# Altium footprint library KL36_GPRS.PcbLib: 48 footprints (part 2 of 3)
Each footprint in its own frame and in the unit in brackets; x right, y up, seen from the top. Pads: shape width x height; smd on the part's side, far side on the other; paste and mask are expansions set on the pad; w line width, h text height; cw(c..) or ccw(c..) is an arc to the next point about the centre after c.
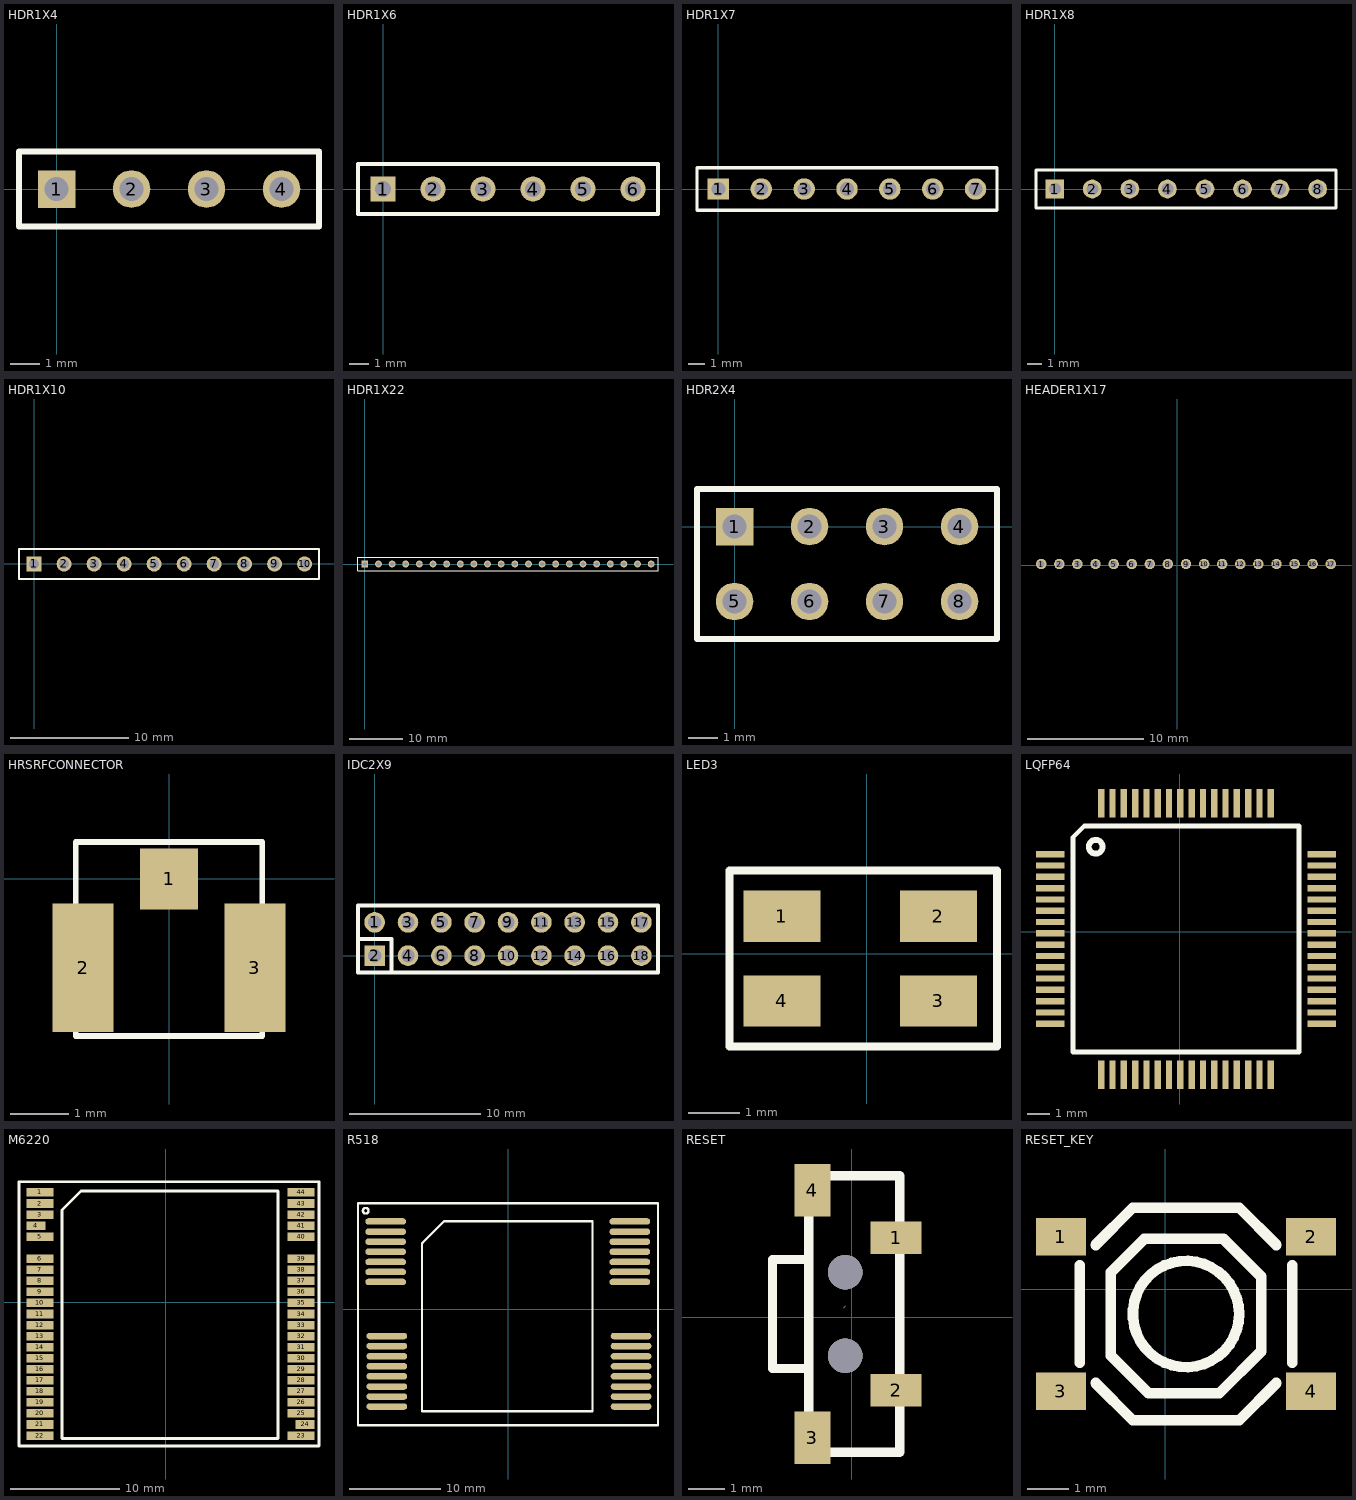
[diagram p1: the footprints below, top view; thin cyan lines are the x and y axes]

## HDR1X4 [mil]
pads (4):
  rect 50x50 hole 32: 1(0,0)
  round 50 hole 32: 2(100,0) 3(200,0) 4(300,0)
Top Overlay:
  lines w7.87: -50,-50 350,-50 350,50 -50,50 -50,-50

## HDR1X6 [mil]
pads (6):
  rect 50x50 hole 32: 1(0,0)
  round 50 hole 32: 2(100,0) 3(200,0) 4(300,0) 5(400,0) 6(500,0)
Top Overlay:
  lines w7.87: -50,-50 550,-50 550,50 -50,50 -50,-50

## HDR1X7 [mil]
pads (7):
  rect 50x50 hole 32: 1(0,0)
  round 50 hole 32: 2(100,0) 3(200,0) 4(300,0) 5(400,0) 6(500,0) 7(600,0)
Top Overlay:
  lines w7.87: -50,-50 -50,50 650,50 650,-50 -50,-50

## HDR1X8 [mil]
pads (8):
  rect 50x50 hole 32: 1(0,0)
  round 50 hole 32: 2(100,0) 3(200,0) 4(300,0) 5(400,0) 6(500,0) 7(600,0) 8(700,0)
Top Overlay:
  lines w7.87: -50,-50 749,-50 749,50 -50,50 -50,-50

## HDR1X10 [mil]
pads (10):
  rect 50x50 hole 32: 1(0,0)
  round 50 hole 32: 2(100,0) 3(200,0) 4(300,0) 5(400,0) 6(500,0) 7(600,0) 8(701,0) 9(801,0) 10(901,0)
Top Overlay:
  lines w7.87: -50,-50 949,-50 949,50 -50,50 -50,-50

## HDR1X22 [mil]
pads (22):
  rect 50x50 hole 32: 1(0,0)
  round 50 hole 32: 2(100,0) 3(200,0) 4(300,0) 5(400,0) 6(500,0) 7(600,0) 8(700,0) 9(800,0) 10(900,0) 11(1000,0) 12(1100,0) 13(1200,0) 14(1300,0) 15(1400,0) 16(1500,0) 17(1600,0) 18(1700,0) 19(1800,0) 20(1900,0) 21(2000,0) 22(2100,0)
Top Overlay:
  lines w7.87: -50,-50 -50,50 25,50 2150,50 2150,-50 -50,-50

## HDR2X4 [mil]
pads (8):
  rect 50x50 hole 32: 1(0,0)
  round 50 hole 32: 2(100,0) 3(200,0) 4(300,0) 5(0,-100) 6(100,-100) 7(200,-100) 8(300,-100)
Top Overlay:
  lines w7.87: -50,-150 350,-150 350,50 -50,50 -50,-150

## HEADER1X17 [mm]
pads (17):
  round 0.9 / inner rect 0.9x1 / far side rect 0.9x2 hole 0.6: 1(-11.733,0.102) 2(-10.173,0.102) 3(-8.613,0.102) 4(-7.053,0.102) 5(-5.493,0.102) 6(-3.933,0.102) 7(-2.373,0.102) 8(-0.813,0.102) 9(0.747,0.102) 10(2.307,0.102) 11(3.867,0.102) 12(5.427,0.102) 13(6.987,0.102) 14(8.547,0.102) 15(10.107,0.102) 16(11.667,0.102) 17(13.227,0.102)

## HRSRFCONNECTOR [mm] "U.FL-R-SMT-1(10)"
height 1.524
pads (3):
  rect 1x1.05 smd: 1(0,0)
  rect 1.05x2.2 smd: 2(-1.475,-1.525) 3(1.475,-1.525)
Top Overlay:
  lines w0.1: -1.6,-2.7 -1.6,0.635 1.6,0.635 1.6,-2.7 -1.6,-2.7

## IDC2X9 [mil]
pads (18):
  round 62 hole 40: 1(0,100) 3(100,100) 4(100,0) 5(200,100) 6(200,0) 7(300,100) 8(300,0) 9(400,100) 10(400,0) 11(500,100) 12(500,0) 13(600,100) 14(600,0) 15(700,100) 16(700,0) 17(800,100) 18(800,0)
  rect 62x62 hole 40: 2(0,0)
Top Overlay:
  lines w12: -50,50 50,50 50,-50 ; -50,-50 850,-50 850,150 -50,150 -50,-50

## LED3 [mil]
pads (5):
  round 40 on Top Overlay: 0(-110,74)
  rect 59.06x39.37 smd: 1(-65,29) 2(55,29) 3(55,-36) 4(-65,-36)
Top Overlay:
  lines w6: -105,-71 100,-71 100,64 -105,64 -105,-71

## LQFP64 [mm]
pads (64):
  rect 1.27x0.28 smd: 1(-5.715,3.429) 2(-5.715,2.929) 3(-5.715,2.429) 4(-5.715,1.929) 5(-5.715,1.429) 6(-5.715,0.929) 7(-5.715,0.429) 8(-5.715,-0.071) 9(-5.715,-0.571) 10(-5.715,-1.071) 11(-5.715,-1.571) 12(-5.715,-2.071) 13(-5.715,-2.571) 14(-5.715,-3.071) 15(-5.715,-3.571) 16(-5.715,-4.071) 33(6.285,-4.071) 34(6.285,-3.571) 35(6.285,-3.071) 36(6.285,-2.571) 37(6.285,-2.071) 38(6.285,-1.571) 39(6.285,-1.071) 40(6.285,-0.571) 41(6.285,-0.071) 42(6.285,0.429) 43(6.285,0.929) 44(6.285,1.429) 45(6.285,1.929) 46(6.285,2.429) 47(6.285,2.929) 48(6.285,3.429)
  rect 0.28x1.27 smd: 17(-3.465,-6.321) 18(-2.965,-6.321) 19(-2.465,-6.321) 20(-1.965,-6.321) 21(-1.465,-6.321) 22(-0.965,-6.321) 23(-0.465,-6.321) 24(0.035,-6.321) 25(0.535,-6.321) 26(1.035,-6.321) 27(1.535,-6.321) 28(2.035,-6.321) 29(2.535,-6.321) 30(3.035,-6.321) 31(3.535,-6.321) 32(4.035,-6.321) 49(4.035,5.679) 50(3.535,5.679) 51(3.035,5.679) 52(2.535,5.679) 53(2.035,5.679) 54(1.535,5.679) 55(1.035,5.679) 56(0.535,5.679) 57(0.035,5.679) 58(-0.465,5.679) 59(-0.965,5.679) 60(-1.465,5.679) 61(-1.965,5.679) 62(-2.465,5.679) 63(-2.965,5.679) 64(-3.465,5.679)
Top Overlay:
  circle w0.254: c-3.709,3.759 r0.306
  lines w0.203: -4.715,-5.321 5.285,-5.321 5.285,4.679 -4.215,4.679 -4.715,4.179 -4.715,-5.321

## M6220 [mil]
pads (44):
  rect 98.43x30.96 smd: 1(-456,397) 2(-456,357) 3(-456,317) 5(-456,237) 6(-456,157) 7(-456,117) 8(-456,77) 9(-456,37) 10(-456,-3) 11(-456,-43) 12(-456,-83) 13(-456,-123) 14(-456,-163) 15(-456,-203) 16(-456,-243) 17(-456,-283) 18(-456,-323) 19(-456,-363) 20(-456,-403) 21(-456,-443) 22(-456,-483) 23(489,-483) 25(489,-403) 26(489,-363) 27(489,-323) 28(489,-283) 29(489,-243) 30(489,-203) 31(489,-163) 32(489,-123) 33(489,-83) 34(489,-43) 35(489,-3) 36(489,37) 37(489,77) 38(489,117) 39(489,157) 40(489,237) 41(489,277) 42(489,317) 43(489,357) 44(489,397)
  rect 68.9x30.96 smd: 4(-471,277) 24(504,-443)
Top Overlay:
  lines w10: -532,-521 -532,436 554,436 554,-521 -532,-521 ; -376,-494 -376,333 -307,402 406,402 406,-494 -376,-494

## R518 [mil]
pads (30):
  oval 175x28 smd: 1(-526,377) 2(-526,333) 3(-526,290) 4(-526,247) 5(-526,203) 6(-526,160) 7(-526,117) 8(-521,-116) 9(-521,-159) 10(-521,-203) 11(-521,-246) 12(-521,-289) 13(-521,-333) 14(-521,-376) 15(-521,-419) 16(529,-419) 17(529,-376) 18(529,-333) 19(529,-289) 20(529,-246) 21(529,-203) 22(529,-159) 23(529,-116) 24(524,117) 25(524,160) 26(524,203) 27(524,247) 28(524,290) 29(524,333) 30(524,377)
Top Overlay:
  circle w10: c-612.04,423 r12.04
  lines w10: -370,-439 -370,282 -369,283 -369,284 -275,378 363,378 363,-439 ; -369,-439 362,-439 ; -645,-499 645,-499 645,455 -645,455 -645,-499

## RESET [mm]
pads (6):
  rect 1.4x0.9 smd: 1(1.216,2.187) 2(1.216,-2.014)
  rect 1x1.45 smd: 3(-1.084,-3.314) 4(-1.084,3.486)
  round 0.95 hole 0.95 unplated: ""(-0.184,-1.064) ""(-0.184,1.236)
Top Overlay:
  lines w0.254: -1.184,-1.414 -2.184,-1.414 -2.184,1.586 -1.184,1.586 ; -1.184,-3.714 1.316,-3.714 1.316,3.886 -1.184,3.886 -1.184,-3.714
Mechanical 15:
  lines w0.003: -0.223,0.257 -0.172,0.308

## RESET_KEY [mil]
pads (4):
  rect 47.2x35.4 smd: 1(-98.4,49.2)
  rect 47.2x35.5 smd: 2(137.82,49.25) 3(-98.4,-96.45) 4(137.82,-96.45)
Top Overlay:
  circle w10: c19.71,-23.6 r50.2
  lines w10: -80.69,-69.6 -80.69,22.4 ; -65.73,-88.76 -30.49,-124 69.91,-124 105.15,-88.76 ; -65.73,41.56 -30.49,76.8 69.91,76.8 105.15,41.56 ; 120.11,-69.6 120.11,22.4 ; -51.19,-62.9 -51.19,15.8 -19.69,47.3 55.11,47.3 90.61,11.8 90.61,-59 51.21,-98.4 -15.69,-98.4 -51.19,-62.9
